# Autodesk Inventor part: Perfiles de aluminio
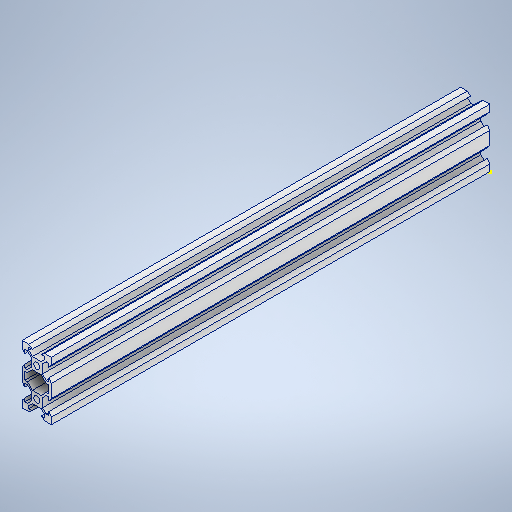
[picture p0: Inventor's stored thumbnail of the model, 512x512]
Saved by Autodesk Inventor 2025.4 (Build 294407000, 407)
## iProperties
Created: 2026-04
Part Number: Perfiles de aluminio
Material: Aluminum 6061
Document SubType Name: Modeling
Designer: I11112
Density: 2.7 g/cm^3
Appearance: Aluminum - Flat
Author: I11112
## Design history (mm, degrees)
sketch "Sketch1"
  geometry: L1 (0, 0)-(20, 0); L2 (20, 0)-(20, 40); L3 (20, 40)-(0, 40); L4 (0, 40)-(0, 0); L5 (13.1, 38.2)-(10, 38.2); L6 (13.1, 38.2)-(15.5, 40); L7 (10, 40)-(10, 0); L8 (13.1, 38.2)-(15.5, 38.2); L9 (20, 40)-(10, 30); L10 (18.2, 33.1)-(20, 35.5); L11 (18.2, 33.1)-(18.2, 35.5); L12 (1.8, 33.1)-(0, 35.5); L13 (1.8, 33.1)-(1.8, 35.5); L14 (6.9, 38.2)-(4.5, 38.2); L15 (6.9, 38.2)-(4.5, 40); L16 (20, 20)-(0, 20); L17 (6.9, 1.8)-(4.5, 1.8); L18 (6.9, 1.8)-(4.5, 0); L19 (1.8, 6.9)-(0, 4.5); L20 (1.8, 6.9)-(1.8, 4.5); L21 (13.1, 1.8)-(10, 1.8); L22 (13.1, 1.8)-(15.5, 1.8); L23 (18.2, 6.9)-(18.2, 4.5); L24 (20, 0)-(0, 0); L25 (20, 0)-(10, 10); L26 (13.1, 1.8)-(15.5, 0); L27 (18.2, 6.9)-(20, 4.5); L28 (6.1, 26.1)-(13.9, 26.1); L29 (13.9, 26.1)-(13.9, 33.9); L30 (13.9, 33.9)-(6.1, 33.9); L31 (6.1, 33.9)-(6.1, 26.1); L32 (6.1, 26.1)-(13.9, 33.9); L33 (13.9, 26.1)-(6.1, 33.9); L34 (4.5, 38.2)-(4.5, 36.4); L35 (4.5, 36.4)-(7, 33.9); L36 (0, 40)-(10, 30); L37 (1.8, 35.5)-(3.6, 35.5); L38 (3.6, 35.5)-(6.1, 33); L39 (15.5, 38.2)-(15.5, 36.4); L40 (15.5, 36.4)-(13, 33.9); L41 (16.4, 35.5)-(13.9, 33); L42 (18.2, 35.5)-(16.4, 35.5); L43 (18.2, 26.9)-(18.2, 24.5); L44 (18.2, 26.9)-(20, 24.5); L45 (16.4, 24.5)-(13.9, 27); L46 (16.4, 35.5)-(13.9, 33); L47 (18.2, 35.5)-(16.4, 35.5); L48 (18.2, 33.1)-(18.2, 35.5); L49 (18.2, 33.1)-(20, 35.5); L50 (18.2, 24.5)-(16.4, 24.5); L51 (3.6, 24.5)-(6.1, 27); L52 (1.8, 24.5)-(3.6, 24.5); L53 (1.8, 26.9)-(1.8, 24.5); L54 (1.8, 26.9)-(0, 24.5); L55 (6.1, 6.1)-(6.1, 13.9); L56 (1.8, 6.9)-(0, 4.5); L57 (3.6, 4.5)-(6.1, 7); L58 (1.8, 4.5)-(3.6, 4.5); L59 (1.8, 6.9)-(1.8, 4.5); L60 (6.1, 13.9)-(13.9, 13.9); L61 (6.1, 13.9)-(13.9, 6.1); L62 (13.9, 13.9)-(6.1, 6.1); L63 (0, 0)-(10, 10); L64 (4.5, 3.6)-(7, 6.1)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; C1 r 2.1 at (10, 30); C2 r 2.1 at (10, 10); C3 r 2.1 at (10, 10); C4 r 2.1 at (10, 10); C5 r 2.1 at (10, 30); 33 further points
  constraints: 260 end point, 83 symmetric about line, 7 midpoint, 7 point on line, 6 horizontal, 5 centre point, 5 parallel, 5 perpendicular, 1 vertical, 4 other
  dimensions: "d0" = 20 distance of L3.end L2.end; "d1" = 40 distance of L2.end L1.end; "d2" = 4.5 distance of L2.end L6.end; "d3" = 3.1 distance from line of L7 L5.start; "d4" = 1.8 distance between parallel lines of L3 L5; "d5" = 2.4 distance of L5.start L8.end; "d6" = 4.2 diameter of C1; "d7" = 10 distance from line of L3 L9.end; "d8" = 7.8 distance of L30.end L29.end; "d9" = 7.8 distance of L29.end L28.end; "d10" = 1.8 distance of L14.end L34.end; "d11" = 1.8 distance from line of point (2.7, 24.5) L95; "d12" = 1.8 vertical distance of point (2.7, 15.5) point (3.15, 17.3)
extrude "Extrusion1" new body sketch "Sketch1" distance "d13" = 300; taper "d14" = 0 deg
sketch "Sketch2"
  geometry: 1 further point
body "Solid1"
